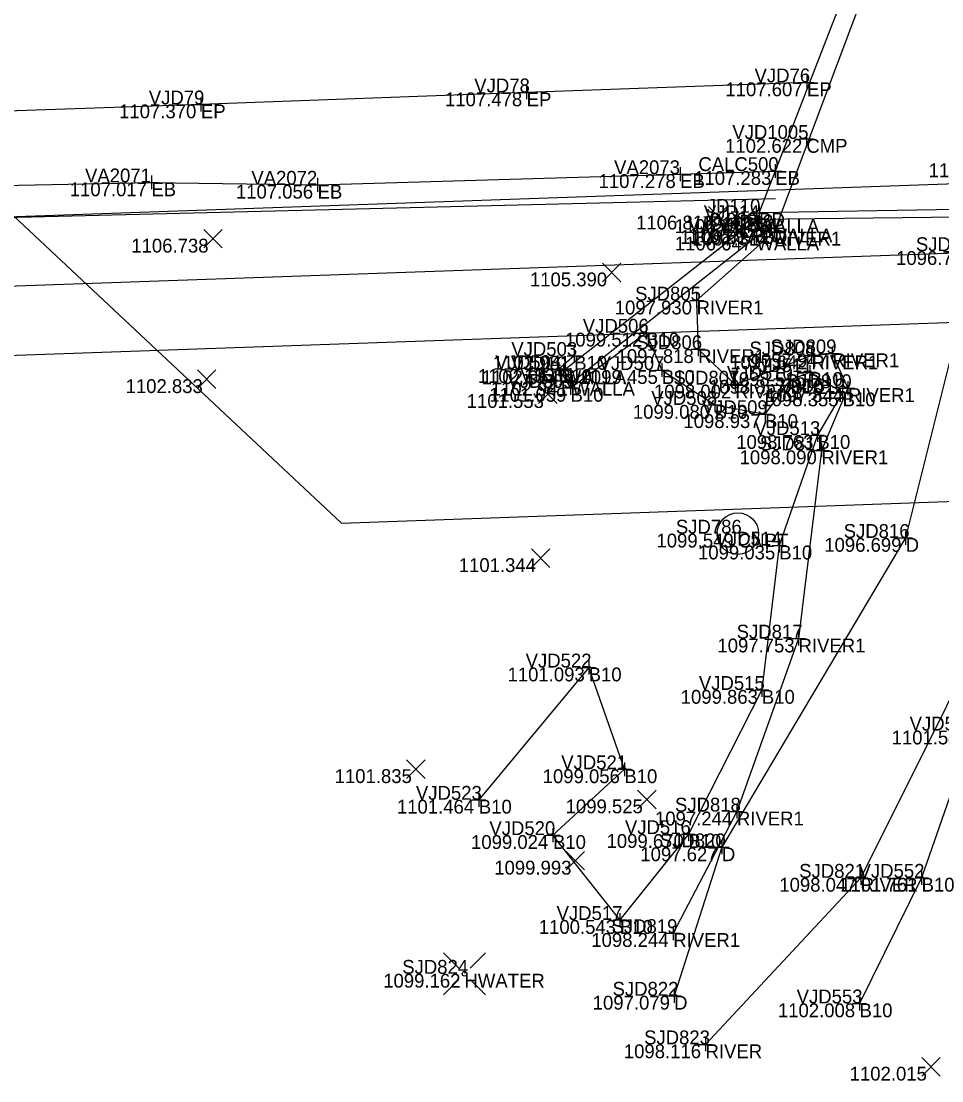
# Model space of a CAD drawing. Extents: x 1629915 to 1630675, y 484401 to 484601.
# Drawn here: x 1630207 to 1630273.5, y 484405.3 to 484481.8 of the extents above; entities that cross this region are included whole.
import ezdxf

# ---------------------------------------------------------------- set-up
doc = ezdxf.new("R2010")
doc.units = 0
for name, color, linetype in [('BR_X_Sub_Foot_Object', 7, 'Continuous'), ('BR_X_Sub_Object', 7, 'Continuous'), ('BR_X_SV_Abut', 7, 'Continuous'), ('BR_X_SV_Deck_Top', 7, 'Continuous'), ('DR_X_Ditch', 7, 'Continuous'), ('GE_X_Cells', 7, 'Continuous'), ('HY_X_Water_Edge', 7, 'Continuous'), ('PV_X_EOP', 7, 'Continuous'), ('PV_X_Shoulder_Aggregate', 7, 'Continuous'), ('RD_X_GR_Rt', 7, 'Continuous'), ('SV_X_Break_Lines', 7, 'Continuous'), ('SV_X_Control_Cells_Found', 7, 'Continuous'), ('SV_X_Random_Point', 7, 'Continuous'), ('SV_X_Shot_Marker', 7, 'Continuous'), ('SV_X_Text_Comment', 7, 'Continuous'), ('SV_X_Text_Elevation', 7, 'Continuous'), ('SV_X_Text_Name', 7, 'Continuous'), ('UT_X_Water', 7, 'Continuous')]:
    doc.layers.add(name, color=color, linetype=linetype)

msp = doc.modelspace()

# ---------------------------------------------------------------- linework, layer by layer
at = {"layer": 'BR_X_Sub_Foot_Object'}
for p, q in [((1629921.46, 484457.7), (1630334.806, 484472.223)), ((1629921.635, 484452.703), (1630334.981, 484467.226)), ((1629921.811, 484447.706), (1630335.157, 484462.229))]:
    msp.add_line(p, q, dxfattribs=at)
at = {"layer": 'BR_X_SV_Abut'}
msp.add_line((1630246.204, 484456.621), (1630260.138, 484467.532), dxfattribs=at)
msp.add_lwpolyline([(1630246.204, 484456.621), (1630246.818, 484455.796), (1630260.13, 484466.277), (1630261.087, 484466.851), (1630260.138, 484467.532), (1630287.545, 484467.838), (1630287.42, 484467.211), (1630290.535, 484455.251), (1630291.626, 484455.474), (1630288.674, 484466.96), (1630288.578, 484467.651)], dxfattribs=at)
at = {"layer": 'BR_X_SV_Deck_Top'}
msp.add_lwpolyline([(1630288.791, 484468.471), (1630260.332, 484468), (1630277.393, 484511.967), (1630305.582, 484512.994), (1630288.334, 484467.836)], dxfattribs=at)
at = {"layer": 'DR_X_Ditch'}
msp.add_lwpolyline([(1630312.285, 484563.174), (1630306.638, 484548.008), (1630304.593, 484540.369), (1630301.212, 484528.393), (1630285.162, 484501.971), (1630282.791, 484487.89), (1630276.09, 484465.226), (1630270.913, 484444.523), (1630257.639, 484422.19), (1630254.188, 484411.475)], dxfattribs=at)
at = {"layer": 'GE_X_Cells'}
msp.add_circle((1630258.794, 484444.833), 1.5, dxfattribs=at)
at = {"layer": 'HY_X_Water_Edge'}
for points in [[(1630309.149, 484564.014), (1630303.907, 484548.371), (1630301.335, 484540.498), (1630297.554, 484530.327), (1630293.047, 484517.737), (1630293.065, 484517.242), (1630286.863, 484512.402), (1630280.864, 484506.48), (1630276.95, 484506.557), (1630270.552, 484490.946), (1630261.424, 484466.626), (1630255.81, 484461.657), (1630255.926, 484458.148), (1630258.606, 484455.59), (1630264.105, 484457.697), (1630265.615, 484457.846), (1630266.742, 484455.334), (1630264.827, 484450.845), (1630263.176, 484437.258), (1630258.725, 484424.768), (1630254.124, 484415.998)], [(1630315.117, 484563.934), (1630310.133, 484547.118), (1630307.022, 484539.287), (1630303.337, 484528.643), (1630300.614, 484515.043), (1630303.987, 484512.284), (1630295.569, 484489.654), (1630286.814, 484467.342), (1630288.813, 484458.618), (1630286.633, 484457.39), (1630280.042, 484444.765), (1630267.68, 484419.987), (1630256.457, 484407.968)]]:
    msp.add_lwpolyline(points, dxfattribs=at)
at = {"layer": 'PV_X_EOP'}
msp.add_lwpolyline([(1630263.784, 484477.407), (1630243.533, 484476.684), (1630220.003, 484475.815), (1630182.217, 484474.501), (1630142.357, 484473.071), (1630102.121, 484471.603), (1630059.531, 484470.186), (1630018.192, 484468.838), (1629978.308, 484467.435), (1629939.56, 484465.905)], dxfattribs=at)
at = {"layer": 'PV_X_Shoulder_Aggregate'}
msp.add_lwpolyline([(1629924.92, 484463.104), (1629930.051, 484463.83), (1629958.351, 484464.985), (1629985.484, 484465.939), (1629989.882, 484465.788), (1629994.282, 484464.53), (1629995.636, 484464.345), (1630011.361, 484464.736), (1630016.574, 484465.202), (1630018.985, 484466.333), (1630028.743, 484467.401), (1630055.537, 484468.29), (1630066.153, 484468.607), (1630075.383, 484468), (1630095.195, 484466.534), (1630119.644, 484467.176), (1630148.034, 484467.946), (1630167.26, 484468.813), (1630191.18, 484469.683), (1630216.422, 484470.188), (1630228.431, 484470.017), (1630254.625, 484470.782), (1630261.494, 484471.006)], dxfattribs=at)
at = {"layer": 'RD_X_GR_Rt'}
msp.add_lwpolyline([(1630142.798, 484466.274), (1630167.072, 484466.684), (1630192.075, 484467.318), (1630261.506, 484469.025)], dxfattribs=at)
at = {"layer": 'SV_X_Break_Lines'}
for points in [[(1630246.969, 484457.662), (1630245.866, 484456.708), (1630246.704, 484455.355), (1630252.174, 484459.338), (1630253.302, 484456.642), (1630257.116, 484454.126), (1630260.752, 484453.457), (1630262.593, 484455.936), (1630263.982, 484456.489), (1630266.359, 484455.025), (1630264.534, 484451.948), (1630261.781, 484443.972), (1630260.525, 484433.552), (1630255.218, 484423.145), (1630250.272, 484416.944), (1630245.436, 484423.07), (1630250.593, 484427.823), (1630248.014, 484435.169), (1630240.08, 484425.622)], [(1630292.722, 484456.186), (1630292.592, 484454.597), (1630291.238, 484453.659), (1630290.531, 484453.124), (1630289.818, 484452.465), (1630288.399, 484452.957), (1630284.791, 484449.461), (1630283.616, 484448.207), (1630282.591, 484443.798), (1630275.76, 484430.619), (1630272.065, 484419.992), (1630267.583, 484410.921)]]:
    msp.add_lwpolyline(points, dxfattribs=at)
at = {"layer": 'SV_X_Control_Cells_Found'}
for p, q in [((1630237.534, 484414.563), (1630238.628, 484413.47)), ((1630239.461, 484413.47), (1630240.553, 484414.563)), ((1630237.534, 484411.545), (1630238.628, 484412.638)), ((1630239.461, 484412.638), (1630240.553, 484411.545))]:
    msp.add_line(p, q, dxfattribs=at)
msp.add_circle((1630239.044, 484413.06), 0.17, dxfattribs=at)
at = {"layer": 'SV_X_Random_Point'}
for p, q in [((1630256.677, 484467.122), (1630258.01, 484468.457)), ((1630256.677, 484468.457), (1630258.01, 484467.122)), ((1630220.206, 484465.455), (1630221.539, 484466.79)), ((1630220.206, 484466.79), (1630221.539, 484465.455)), ((1630249.014, 484463.016), (1630250.347, 484464.351)), ((1630249.014, 484464.351), (1630250.347, 484463.016)), ((1630219.757, 484455.314), (1630221.09, 484456.649)), ((1630219.757, 484456.649), (1630221.09, 484455.314)), ((1630244.399, 484454.237), (1630245.732, 484455.572)), ((1630244.399, 484455.572), (1630245.732, 484454.237)), ((1630243.883, 484442.395), (1630245.216, 484443.73)), ((1630243.883, 484443.73), (1630245.216, 484442.395)), ((1630234.864, 484427.163), (1630236.197, 484428.498)), ((1630234.864, 484428.498), (1630236.197, 484427.163)), ((1630251.552, 484424.978), (1630252.885, 484426.313)), ((1630251.552, 484426.313), (1630252.885, 484424.978)), ((1630246.387, 484420.554), (1630247.721, 484421.889)), ((1630246.387, 484421.889), (1630247.721, 484420.554)), ((1630272.07, 484405.682), (1630273.403, 484407.017)), ((1630272.07, 484407.017), (1630273.403, 484405.682))]:
    msp.add_line(p, q, dxfattribs=at)
at = {"layer": 'SV_X_Shot_Marker'}
for p, q in [((1630263.784, 484477.907), (1630263.784, 484476.907)), ((1630243.533, 484477.184), (1630243.533, 484476.184)), ((1630263.284, 484477.407), (1630264.284, 484477.407)), ((1630263.784, 484477.407), (1630263.784, 484477.407)), ((1630220.003, 484476.315), (1630220.003, 484475.315)), ((1630243.033, 484476.684), (1630244.033, 484476.684)), ((1630243.533, 484476.684), (1630243.533, 484476.684)), ((1630219.503, 484475.815), (1630220.503, 484475.815)), ((1630220.003, 484475.815), (1630220.003, 484475.815)), ((1630263.741, 484473.825), (1630263.741, 484472.825)), ((1630263.241, 484473.325), (1630264.241, 484473.325)), ((1630263.741, 484473.325), (1630263.741, 484473.325)), ((1630261.494, 484471.506), (1630261.494, 484470.506)), ((1630216.422, 484470.688), (1630216.422, 484469.688)), ((1630254.125, 484470.782), (1630255.125, 484470.782)), ((1630254.625, 484471.282), (1630254.625, 484470.282)), ((1630254.625, 484470.782), (1630254.625, 484470.782)), ((1630260.994, 484471.006), (1630261.994, 484471.006)), ((1630261.494, 484471.006), (1630261.494, 484471.006)), ((1630215.922, 484470.188), (1630216.922, 484470.188)), ((1630216.422, 484470.188), (1630216.422, 484470.188)), ((1630227.931, 484470.017), (1630228.931, 484470.017)), ((1630228.431, 484470.517), (1630228.431, 484469.517)), ((1630228.431, 484470.017), (1630228.431, 484470.017)), ((1630260.332, 484468.5), (1630260.332, 484467.5)), ((1630259.638, 484467.532), (1630260.638, 484467.532)), ((1630259.832, 484468), (1630260.832, 484468)), ((1630260.138, 484468.032), (1630260.138, 484467.032)), ((1630260.138, 484467.532), (1630260.138, 484467.532)), ((1630260.332, 484468), (1630260.332, 484468)), ((1630260.012, 484466.744), (1630261.012, 484466.744)), ((1630260.13, 484466.777), (1630260.13, 484465.777)), ((1630260.512, 484467.244), (1630260.512, 484466.244)), ((1630260.512, 484466.744), (1630260.512, 484466.744)), ((1630260.587, 484466.851), (1630261.587, 484466.851)), ((1630261.087, 484467.351), (1630261.087, 484466.351)), ((1630261.087, 484466.851), (1630261.087, 484466.851)), ((1630261.424, 484467.126), (1630261.424, 484466.126)), ((1630259.63, 484466.277), (1630260.63, 484466.277)), ((1630260.13, 484466.277), (1630260.13, 484466.277)), ((1630260.924, 484466.626), (1630261.924, 484466.626)), ((1630261.424, 484466.626), (1630261.424, 484466.626)), ((1630255.81, 484462.157), (1630255.81, 484461.157)), ((1630255.31, 484461.657), (1630256.31, 484461.657)), ((1630255.81, 484461.657), (1630255.81, 484461.657)), ((1630251.674, 484459.338), (1630252.674, 484459.338)), ((1630252.174, 484459.838), (1630252.174, 484458.838)), ((1630252.174, 484459.338), (1630252.174, 484459.338)), ((1630255.926, 484458.648), (1630255.926, 484457.648)), ((1630265.615, 484458.346), (1630265.615, 484457.346)), ((1630246.469, 484457.662), (1630247.469, 484457.662)), ((1630246.969, 484458.162), (1630246.969, 484457.162)), ((1630246.969, 484457.662), (1630246.969, 484457.662)), ((1630255.426, 484458.148), (1630256.426, 484458.148)), ((1630255.926, 484458.148), (1630255.926, 484458.148)), ((1630263.605, 484457.697), (1630264.605, 484457.697)), ((1630264.105, 484458.197), (1630264.105, 484457.197)), ((1630264.105, 484457.697), (1630264.105, 484457.697)), ((1630265.115, 484457.846), (1630266.115, 484457.846)), ((1630265.615, 484457.846), (1630265.615, 484457.846)), ((1630245.866, 484457.208), (1630245.866, 484456.208)), ((1630246.204, 484457.121), (1630246.204, 484456.121)), ((1630253.302, 484457.142), (1630253.302, 484456.142)), ((1630263.982, 484456.989), (1630263.982, 484455.989)), ((1630245.366, 484456.708), (1630246.366, 484456.708)), ((1630245.704, 484456.621), (1630246.704, 484456.621)), ((1630245.866, 484456.708), (1630245.866, 484456.708)), ((1630246.204, 484456.621), (1630246.204, 484456.621)), ((1630246.818, 484456.296), (1630246.818, 484455.296)), ((1630252.802, 484456.642), (1630253.802, 484456.642)), ((1630253.302, 484456.642), (1630253.302, 484456.642)), ((1630258.606, 484456.09), (1630258.606, 484455.09)), ((1630262.593, 484456.436), (1630262.593, 484455.436)), ((1630263.482, 484456.489), (1630264.482, 484456.489)), ((1630263.982, 484456.489), (1630263.982, 484456.489)), ((1630246.204, 484455.355), (1630247.204, 484455.355)), ((1630246.318, 484455.796), (1630247.318, 484455.796)), ((1630246.704, 484455.855), (1630246.704, 484454.855)), ((1630246.704, 484455.355), (1630246.704, 484455.355)), ((1630246.818, 484455.796), (1630246.818, 484455.796)), ((1630258.106, 484455.59), (1630259.106, 484455.59)), ((1630258.606, 484455.59), (1630258.606, 484455.59)), ((1630262.093, 484455.936), (1630263.093, 484455.936)), ((1630262.593, 484455.936), (1630262.593, 484455.936)), ((1630266.242, 484455.334), (1630267.242, 484455.334)), ((1630266.359, 484455.525), (1630266.359, 484454.525)), ((1630266.742, 484455.834), (1630266.742, 484454.834)), ((1630266.742, 484455.334), (1630266.742, 484455.334)), ((1630257.116, 484454.626), (1630257.116, 484453.626)), ((1630265.859, 484455.025), (1630266.859, 484455.025)), ((1630266.359, 484455.025), (1630266.359, 484455.025)), ((1630256.616, 484454.126), (1630257.616, 484454.126)), ((1630257.116, 484454.126), (1630257.116, 484454.126)), ((1630260.752, 484453.957), (1630260.752, 484452.957)), ((1630260.252, 484453.457), (1630261.252, 484453.457)), ((1630260.752, 484453.457), (1630260.752, 484453.457)), ((1630264.534, 484452.448), (1630264.534, 484451.448)), ((1630264.034, 484451.948), (1630265.034, 484451.948)), ((1630264.534, 484451.948), (1630264.534, 484451.948)), ((1630264.327, 484450.845), (1630265.327, 484450.845)), ((1630264.827, 484451.345), (1630264.827, 484450.345)), ((1630264.827, 484450.845), (1630264.827, 484450.845)), ((1630270.913, 484445.023), (1630270.913, 484444.023)), ((1630261.281, 484443.972), (1630262.281, 484443.972)), ((1630261.781, 484444.472), (1630261.781, 484443.472)), ((1630261.781, 484443.972), (1630261.781, 484443.972)), ((1630270.413, 484444.523), (1630271.413, 484444.523)), ((1630270.913, 484444.523), (1630270.913, 484444.523)), ((1630263.176, 484437.758), (1630263.176, 484436.758)), ((1630262.676, 484437.258), (1630263.676, 484437.258)), ((1630263.176, 484437.258), (1630263.176, 484437.258)), ((1630248.014, 484435.669), (1630248.014, 484434.669)), ((1630247.514, 484435.169), (1630248.514, 484435.169)), ((1630248.014, 484435.169), (1630248.014, 484435.169)), ((1630260.525, 484434.052), (1630260.525, 484433.052)), ((1630260.025, 484433.552), (1630261.025, 484433.552)), ((1630260.525, 484433.552), (1630260.525, 484433.552)), ((1630250.093, 484427.823), (1630251.093, 484427.823)), ((1630250.593, 484428.323), (1630250.593, 484427.323)), ((1630250.593, 484427.823), (1630250.593, 484427.823)), ((1630239.58, 484425.622), (1630240.58, 484425.622)), ((1630240.08, 484426.122), (1630240.08, 484425.122)), ((1630240.08, 484425.622), (1630240.08, 484425.622)), ((1630258.225, 484424.768), (1630259.225, 484424.768)), ((1630258.725, 484425.268), (1630258.725, 484424.268)), ((1630258.725, 484424.768), (1630258.725, 484424.768)), ((1630245.436, 484423.57), (1630245.436, 484422.57)), ((1630254.718, 484423.145), (1630255.718, 484423.145)), ((1630255.218, 484423.645), (1630255.218, 484422.645)), ((1630255.218, 484423.145), (1630255.218, 484423.145)), ((1630244.936, 484423.07), (1630245.936, 484423.07)), ((1630245.436, 484423.07), (1630245.436, 484423.07)), ((1630257.639, 484422.69), (1630257.639, 484421.69)), ((1630257.139, 484422.19), (1630258.139, 484422.19)), ((1630257.639, 484422.19), (1630257.639, 484422.19)), ((1630267.68, 484420.487), (1630267.68, 484419.487)), ((1630272.065, 484420.492), (1630272.065, 484419.492)), ((1630267.18, 484419.987), (1630268.18, 484419.987)), ((1630267.68, 484419.987), (1630267.68, 484419.987)), ((1630271.565, 484419.992), (1630272.565, 484419.992)), ((1630272.065, 484419.992), (1630272.065, 484419.992)), ((1630250.272, 484417.444), (1630250.272, 484416.444)), ((1630249.772, 484416.944), (1630250.772, 484416.944)), ((1630250.272, 484416.944), (1630250.272, 484416.944)), ((1630254.124, 484416.498), (1630254.124, 484415.498)), ((1630253.624, 484415.998), (1630254.624, 484415.998)), ((1630254.124, 484415.998), (1630254.124, 484415.998)), ((1630254.188, 484411.975), (1630254.188, 484410.975)), ((1630253.688, 484411.475), (1630254.688, 484411.475)), ((1630254.188, 484411.475), (1630254.188, 484411.475)), ((1630267.083, 484410.921), (1630268.083, 484410.921)), ((1630267.583, 484411.421), (1630267.583, 484410.421)), ((1630267.583, 484410.921), (1630267.583, 484410.921)), ((1630255.957, 484407.968), (1630256.957, 484407.968)), ((1630256.457, 484408.468), (1630256.457, 484407.468)), ((1630256.457, 484407.968), (1630256.457, 484407.968))]:
    msp.add_line(p, q, dxfattribs=at)
at = {"layer": 'UT_X_Water'}
for p, q in [((1630200.605, 484473.262), (1630230.15, 484445.587)), ((1630230.15, 484445.587), (1630302.544, 484448.189))]:
    msp.add_line(p, q, dxfattribs=at)

# ---------------------------------------------------------------- texts
at = {"layer": 'BR_X_Sub_Object'}
for s, p in [('VJD14', (1630256.334, 484467.532)), ('JD110', (1630256.55, 484468)), ('1106.724', (1630254.218, 484466.532)), ('VJD1003', (1630255.17, 484466.744)), ('0.000', (1630256.814, 484467)), ('VJD13', (1630257.342, 484466.851)), ('WALLA', (1630260.138, 484466.532)), ('BD', (1630260.332, 484467)), ('1106.917', (1630254.618, 484465.744)), ('1106.973', (1630255.225, 484465.851)), ('VJD12', (1630256.375, 484466.277)), ('BD', (1630260.512, 484465.744)), ('WALLA', (1630261.087, 484465.851)), ('1106.647', (1630254.236, 484465.277)), ('WALLA', (1630260.13, 484465.277)), ('VJD10', (1630242.409, 484456.621)), ('1102.964', (1630240.284, 484455.621)), ('VJD11', (1630243.055, 484455.796)), ('WALLA', (1630246.204, 484455.621)), ('1102.941', (1630240.938, 484454.796)), ('WALLA', (1630246.818, 484454.796))]:
    msp.add_text(s, height=1, dxfattribs=at).set_placement(p)
at = {"layer": 'SV_X_Text_Comment'}
for s, p in [('EP', (1630263.784, 484476.407)), ('EP', (1630243.533, 484475.684)), ('EP', (1630220.003, 484474.815)), ('CMP', (1630263.741, 484472.325)), ('EB', (1630254.625, 484469.782)), ('EB', (1630261.494, 484470.006)), ('EB', (1630216.422, 484469.188)), ('EB', (1630228.431, 484469.017)), ('RIVER1', (1630261.424, 484465.626)), ('RIVER1', (1630255.81, 484460.657)), ('B10', (1630252.174, 484458.338)), ('B10', (1630246.969, 484456.662)), ('RIVER1', (1630255.926, 484457.148)), ('RIVER1', (1630264.105, 484456.697)), ('RIVER1', (1630265.615, 484456.846)), ('B10', (1630245.866, 484455.708)), ('B10', (1630253.302, 484455.642)), ('B10', (1630263.982, 484455.489)), ('B10', (1630246.704, 484454.355)), ('RIVER1', (1630258.606, 484454.59)), ('B10', (1630262.593, 484454.936)), ('RIVER1', (1630266.742, 484454.334)), ('B10', (1630266.359, 484454.025)), ('B10', (1630257.116, 484453.126)), ('B10', (1630260.752, 484452.457)), ('B10', (1630264.534, 484450.948)), ('RIVER1', (1630264.827, 484449.845)), ('CNPT', (1630258.794, 484443.833)), ('B10', (1630261.781, 484442.972)), ('D', (1630270.913, 484443.523)), ('RIVER1', (1630263.176, 484436.258)), ('B10', (1630248.014, 484434.169)), ('B10', (1630260.525, 484432.552)), ('B10', (1630250.593, 484426.823)), ('B10', (1630240.08, 484424.622)), ('RIVER1', (1630258.725, 484423.768)), ('B10', (1630255.218, 484422.145)), ('B10', (1630245.436, 484422.07)), ('D', (1630257.639, 484421.19)), ('RIVER', (1630267.68, 484418.987)), ('B10', (1630272.065, 484418.992)), ('B10', (1630250.272, 484415.944)), ('RIVER1', (1630254.124, 484414.998)), ('HWATER', (1630239.044, 484412.06)), ('D', (1630254.188, 484410.475)), ('B10', (1630267.583, 484409.921)), ('RIVER', (1630256.457, 484406.968))]:
    msp.add_text(s, height=1, dxfattribs=at).set_placement(p)
at = {"layer": 'SV_X_Text_Elevation'}
for s, p in [('1107.478', (1630237.635, 484475.684)), ('1107.607', (1630257.89, 484476.407)), ('1107.370', (1630214.092, 484474.815)), ('1102.622', (1630257.869, 484472.325)), ('1107.296', (1630272.572, 484470.561)), ('1107.278', (1630248.726, 484469.782)), ('1107.283', (1630255.632, 484470.006)), ('1107.017', (1630210.528, 484469.188)), ('1107.056', (1630222.529, 484469.017)), ('1106.816', (1630251.441, 484466.79)), ('1106.738', (1630214.974, 484465.122)), ('1097.314', (1630255.503, 484465.626)), ('1096.762', (1630270.219, 484464.226)), ('1105.390', (1630243.769, 484462.684)), ('1097.930', (1630249.898, 484460.657)), ('1099.512', (1630246.303, 484458.338)), ('1102.981', (1630241.089, 484456.662)), ('1097.818', (1630250.028, 484457.148)), ('1097.642', (1630258.234, 484456.697)), ('1097.947', (1630259.721, 484456.846)), ('1102.133', (1630240.004, 484455.708)), ('1099.455', (1630247.433, 484455.642)), ('1098.515', (1630258.113, 484455.489)), ('1102.833', (1630214.561, 484454.981)), ('1101.059', (1630240.822, 484454.355)), ('1098.002', (1630252.735, 484454.59)), ('1098.857', (1630256.699, 484454.936)), ('1097.844', (1630260.821, 484454.334)), ('1101.553', (1630239.204, 484453.905)), ('1098.355', (1630260.491, 484454.025)), ('1099.080', (1630251.205, 484453.126)), ('1098.937', (1630254.858, 484452.457)), ('1098.763', (1630258.672, 484450.948)), ('1098.090', (1630258.915, 484449.845)), ('1099.549', (1630252.912, 484443.833)), ('1099.035', (1630255.913, 484442.972)), ('1096.699', (1630265.032, 484443.523)), ('1101.344', (1630238.629, 484442.062)), ('1097.753', (1630257.314, 484436.258)), ('1101.093', (1630242.152, 484434.169)), ('1099.863', (1630254.663, 484432.552)), ('1101.543', (1630269.898, 484429.619)), ('1101.835', (1630229.662, 484426.83)), ('1099.056', (1630244.691, 484426.823)), ('1101.464', (1630234.159, 484424.622)), ('1099.525', (1630246.35, 484424.646)), ('1097.244', (1630252.805, 484423.768)), ('1099.670', (1630249.306, 484422.145)), ('1099.024', (1630239.516, 484422.07)), ('1097.627', (1630251.746, 484421.19)), ('1099.993', (1630241.192, 484420.222)), ('1098.047', (1630261.786, 484418.987)), ('1101.761', (1630266.185, 484418.992)), ('1100.543', (1630244.41, 484415.944)), ('1098.244', (1630248.204, 484414.998)), ('1099.162', (1630233.173, 484412.06)), ('1097.079', (1630248.306, 484410.475)), ('1102.008', (1630261.684, 484409.921)), ('1098.116', (1630250.554, 484406.968)), ('1102.015', (1630266.868, 484405.349))]:
    msp.add_text(s, height=1, dxfattribs=at).set_placement(p)
at = {"layer": 'SV_X_Text_Name'}
for s, p in [('VJD76', (1630259.998, 484477.407)), ('VJD78', (1630239.751, 484476.684)), ('VJD79', (1630216.238, 484475.815)), ('VJD1005', (1630258.392, 484473.325)), ('VA2073', (1630249.85, 484470.782)), ('CALC500', (1630255.94, 484471.006)), ('VA2071', (1630211.63, 484470.188)), ('VA2072', (1630223.647, 484470.017)), ('SJD804', (1630256.927, 484466.626)), ('SJD803', (1630271.652, 484465.226)), ('SJD805', (1630251.365, 484461.657)), ('VJD506', (1630247.59, 484459.338)), ('SJD806', (1630251.447, 484458.148)), ('VJD503', (1630242.425, 484457.662)), ('SJD808', (1630259.63, 484457.697)), ('SJD809', (1630261.157, 484457.846)), ('VJD504', (1630241.264, 484456.708)), ('VJD507', (1630248.726, 484456.642)), ('VJD510', (1630257.999, 484455.936)), ('VJD511', (1630259.42, 484456.489)), ('VJD505', (1630242.154, 484455.355)), ('SJD807', (1630254.136, 484455.59)), ('VJD512', (1630261.806, 484455.025)), ('SJD810', (1630262.253, 484455.334)), ('VJD508', (1630252.536, 484454.126)), ('VJD509', (1630256.189, 484453.457)), ('VJD513', (1630259.99, 484451.948)), ('SJD811', (1630260.371, 484450.845)), ('SJD786', (1630254.315, 484444.833)), ('SJD816', (1630266.434, 484444.523)), ('VJD514', (1630257.18, 484443.972)), ('SJD817', (1630258.706, 484437.258)), ('VJD522', (1630243.461, 484435.169)), ('VJD515', (1630255.975, 484433.552)), ('VJD551', (1630271.199, 484430.619)), ('VJD521', (1630246.031, 484427.823)), ('VJD523', (1630235.536, 484425.622)), ('SJD818', (1630254.25, 484424.768)), ('VJD520', (1630240.842, 484423.07)), ('VJD516', (1630250.634, 484423.145)), ('SJD820', (1630253.151, 484422.19)), ('SJD821', (1630263.224, 484419.987)), ('VJD552', (1630267.512, 484419.992)), ('VJD517', (1630245.696, 484416.944)), ('SJD819', (1630249.666, 484415.998)), ('SJD824', (1630234.548, 484413.06)), ('SJD822', (1630249.74, 484411.475)), ('VJD553', (1630263.039, 484410.921)), ('SJD823', (1630252.018, 484407.968))]:
    msp.add_text(s, height=1, dxfattribs=at).set_placement(p)

doc.saveas('drawing.dxf')
